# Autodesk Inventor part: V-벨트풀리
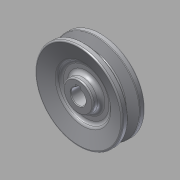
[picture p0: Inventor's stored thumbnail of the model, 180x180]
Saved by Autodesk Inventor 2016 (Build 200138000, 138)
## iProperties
Created: 2016-08
Part Number: V-벨트풀리
Material: 알루미늄 6061
Document SubType Name: Modeling
Designer: mduedu
Density: 2.71 g/cm^3
Appearance: 알루미늄 - 평지
Author: mduedu
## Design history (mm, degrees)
sketch "스케치1"
  geometry: L1 (0, 9.5)-(0, -9.5); L2 (0, 9.5)-(35, 9.5); L3 (35, 9.5)-(35, 4.825); L4 (35, 4.825)-(26, 2.074); L5 (26, 2.074)-(26, 0); L6 (0, 0)-(26, 0); L7 (0, -9.5)-(35, -9.5); L8 (35, -9.5)-(35, -4.825); L9 (35, -4.825)-(26, -2.074); L10 (26, -2.074)-(26, 0); L11 (32.3, 9.5)-(32.3, -9.5); 3 further points
  constraints: 22 end point, 6 point on line, 4 perpendicular, 3 symmetric about line, 1 coincident, 1 horizontal alignment, 1 midpoint, 1 parallel, 1 vertical
  dimensions: "d0" = 19 distance of L1.start L1.end; "d2" = 70 diameter of L8 L1; "d4" = 6.3 distance between parallel lines of L10 L11; "d5" = 2.7 distance between parallel lines of L11 L8; "d6" = 8 distance of point (32.3, -4) point (32.3, 4); "d7" = 34 deg angle of L9 L4
revolve "회전1" sketch "스케치1" stored, may be unused: angle "d8" = 90 deg
sketch "스케치2"
  geometry: L1 (-2, 0)-(2, 0); L2 (2, 0)-(2, 7.8); L3 (2, 7.8)-(-2, 7.8); L4 (-2, 7.8)-(-2, 0); C1 r 6 at (0, 0); 2 further points
  constraints: 8 end point, 2 coincident, 2 parallel, 1 centre point, 1 horizontal, 1 midpoint, 1 perpendicular
  dimensions: "d9" = 12 diameter of C1; "d11" = 4 distance of L2.end L3.end; "d12" = 7.8 distance of L1.end L2.end
extrude "돌출1" cut sketch "스케치2" stored distance "d13" = 10; taper "d14" = 0 deg
sketch "스케치3"
  geometry: L1 (35, 4.825)-(26, 2.074) reference; L2 (26, 2.074)-(26, -2.074) reference; L3 (0, 0)-(26, 0); L4 (35, 9.5)-(35, 4.825) reference; L5 (-35, 9.5)-(35, 9.5) reference; L6 (35, 9.5)-(21, 5.22); L7 (21, 5.22)-(21, 3); L8 (21, 3)-(12, 3); L9 (12, 3)-(12, 9.5); L10 (0, 9.5)-(0, -9.5); L11 (5.657, -9.5)-(-6, -9.5) reference; L12 (12, 9.5)-(35, 9.5)
  constraints: 14 end point, 3 midpoint, 2 parallel, 2 perpendicular, 2 point on line, 1 collinear, 1 horizontal
  dimensions: "d15" = 3 distance between parallel lines of L3 L8; "d17" = 42 diameter of L7 L10; "d18" = 24 diameter of L9 L10
revolve "회전2" sketch "스케치3" stored, may be unused: angle "d19" = 90 deg
fillet "모깎기1" dims "d20" = 0.5, "d21" = 1, "d22" = 1
fillet "모깎기2" dims "d23" = 3
fillet "모깎기3" dims "d24" = 3
fillet "모깎기4" dims "d25" = 3
chamfer "모따기1" distance "d26" = 0.5; stored, may be unused: second distance "d27" = 2, angle "d28" = 45 deg
fillet "모깎기5" dims "d29" = 1
node "솔리드1"
mirror "대칭1"
